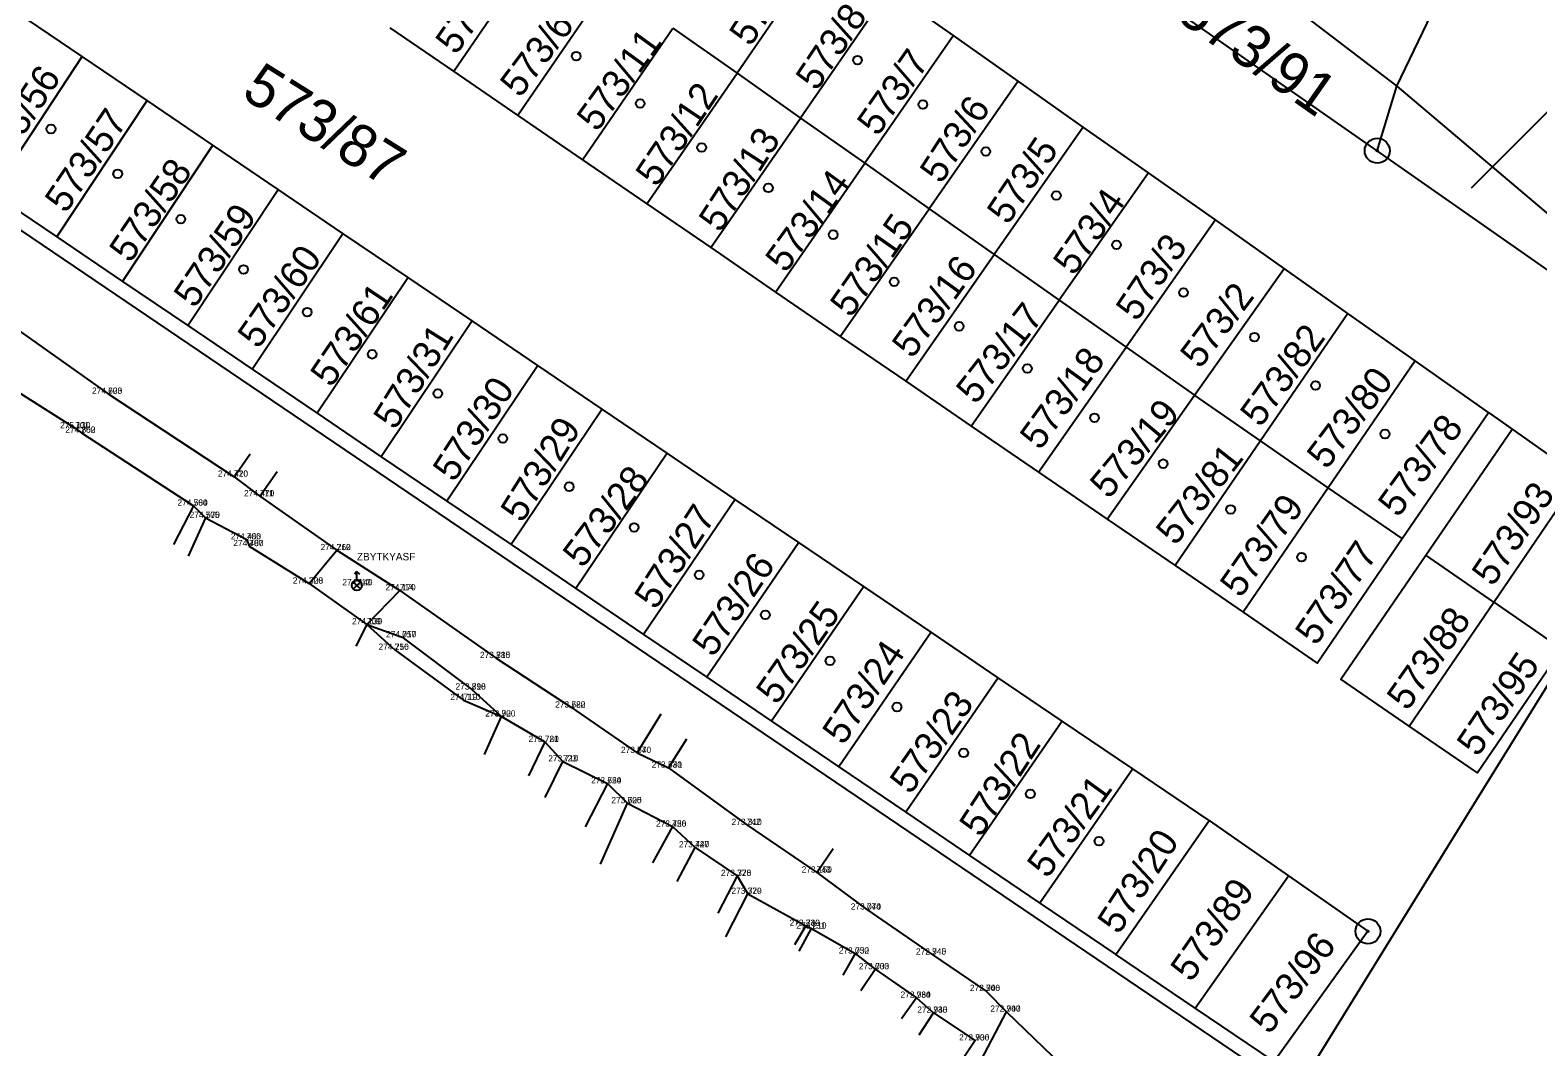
# Model space of a CAD drawing. Extents: x -776701 to -776081, y -974398 to -973771.
# Drawn here: x -776402.9 to -776342.5, y -974069 to -974028.3 of the extents above; entities that cross this region are included whole.
import ezdxf

# ---------------------------------------------------------------- set-up
doc = ezdxf.new("R2010")
doc.units = 0
for name, color, linetype in [('1 Body-bod', 7, 'Continuous'), ('10 Silnice-chodniky', 7, 'Continuous'), ('11 Rozhrani-nezpev zpev schody', 7, 'Continuous'), ('14 Hrany-paty svahu', 7, 'Continuous'), ('2 Body-cislo', 7, 'Continuous'), ('3 Body-vyska', 7, 'Continuous'), ('40 Popis-povrch', 7, 'Continuous'), ('58 Mobiliar', 7, 'Continuous'), ('7 Ploty', 7, 'Continuous'), ('Hranice parcel', 7, 'Continuous'), ('Parcelní čísla', 7, 'Continuous'), ('Pop  PČ popisy', 7, 'Continuous'), ('Značky bodu BP', 7, 'Continuous'), ('Značky budov', 7, 'Continuous')]:
    doc.layers.add(name, color=color, linetype=linetype)

msp = doc.modelspace()

# ---------------------------------------------------------------- linework, layer by layer
at = {"layer": '1 Body-bod'}
for p, q in [((-776399.75, -974042.85), (-776399.75, -974042.85)), ((-776401.07, -974044.23), (-776401.07, -974044.23)), ((-776400.82, -974044.41), (-776400.82, -974044.41)), ((-776394.71, -974046.17), (-776394.71, -974046.17)), ((-776393.68, -974046.95), (-776393.68, -974046.95)), ((-776396.33, -974047.33), (-776396.33, -974047.33)), ((-776395.85, -974047.82), (-776395.85, -974047.82)), ((-776394.2, -974048.68), (-776394.2, -974048.68)), ((-776394.1, -974048.95), (-776394.1, -974048.95)), ((-776390.6, -974049.11), (-776390.6, -974049.11)), ((-776391.7, -974050.45), (-776391.7, -974050.45)), ((-776389.79, -974050.52), (-776389.79, -974050.52)), ((-776388.07, -974050.72), (-776388.07, -974050.72)), ((-776389.39, -974052.08), (-776389.39, -974052.08)), ((-776387.98, -974052.6), (-776387.98, -974052.6)), ((-776388.27, -974053.1), (-776388.27, -974053.1)), ((-776384.21, -974053.43), (-776384.21, -974053.43)), ((-776385.52, -974055.11), (-776385.52, -974055.11)), ((-776385.19, -974054.69), (-776385.19, -974054.69)), ((-776381.2, -974055.41), (-776381.2, -974055.41)), ((-776384, -974055.77), (-776384, -974055.77)), ((-776382.27, -974056.79), (-776382.27, -974056.79)), ((-776381.54, -974057.57), (-776381.54, -974057.57)), ((-776378.57, -974057.23), (-776378.57, -974057.23)), ((-776377.32, -974057.82), (-776377.32, -974057.82)), ((-776379.76, -974058.45), (-776379.76, -974058.45)), ((-776378.95, -974059.24), (-776378.95, -974059.24)), ((-776377.16, -974060.18), (-776377.16, -974060.18)), ((-776374.18, -974060.11), (-776374.18, -974060.11)), ((-776376.25, -974061.01), (-776376.25, -974061.01)), ((-776374.56, -974062.15), (-776374.56, -974062.15)), ((-776371.38, -974062.02), (-776371.38, -974062.02)), ((-776374.14, -974062.87), (-776374.14, -974062.87)), ((-776369.37, -974063.5), (-776369.37, -974063.5)), ((-776371.81, -974064.15), (-776371.81, -974064.15)), ((-776371.59, -974064.26), (-776371.59, -974064.26)), ((-776369.84, -974065.26), (-776369.84, -974065.26)), ((-776366.76, -974065.3), (-776366.76, -974065.3)), ((-776369.04, -974065.89), (-776369.04, -974065.89)), ((-776367.38, -974067.03), (-776367.38, -974067.03)), ((-776364.6, -974066.76), (-776364.6, -974066.76)), ((-776366.71, -974067.63), (-776366.71, -974067.63)), ((-776363.78, -974067.59), (-776363.78, -974067.59)), ((-776365.03, -974068.74), (-776365.03, -974068.74))]:
    msp.add_line(p, q, dxfattribs=at)
at = {"layer": '10 Silnice-chodniky'}
for points in [[(-776391.7, -974050.45), (-776390.6, -974049.11)], [(-776389.39, -974052.08), (-776388.07, -974050.72)], [(-776364.95, -974069.84), (-776363.78, -974067.59), (-776361.2, -974070.08), (-776356.9, -974074.58)]]:
    msp.add_lwpolyline(points, dxfattribs=at)
at = {"layer": '11 Rozhrani-nezpev zpev schody'}
for points in [[(-776401.07, -974044.23), (-776400.82, -974044.41)], [(-776394.71, -974046.17), (-776393.68, -974046.95)], [(-776396.33, -974047.33), (-776395.85, -974047.82)], [(-776389.39, -974052.08), (-776387.98, -974052.6), (-776385.19, -974054.69), (-776384, -974055.77)], [(-776382.27, -974056.79), (-776381.54, -974057.57)], [(-776378.57, -974057.23), (-776377.32, -974057.82)], [(-776379.76, -974058.45), (-776378.95, -974059.24)], [(-776377.16, -974060.18), (-776376.25, -974061.01)], [(-776374.56, -974062.15), (-776374.14, -974062.87)], [(-776371.38, -974062.02), (-776369.37, -974063.5), (-776366.76, -974065.3), (-776364.6, -974066.76), (-776363.78, -974067.59)], [(-776371.81, -974064.15), (-776371.59, -974064.26)], [(-776369.84, -974065.26), (-776369.04, -974065.89)], [(-776367.38, -974067.03), (-776366.71, -974067.63)]]:
    msp.add_lwpolyline(points, dxfattribs=at)
at = {"layer": '14 Hrany-paty svahu'}
msp.add_lwpolyline([(-776389.39, -974052.08), (-776388.27, -974053.1), (-776385.52, -974055.11), (-776384, -974055.77)], dxfattribs=at)
at = {"layer": '58 Mobiliar'}
for p, q in [((-776389.79, -974049.97), (-776389.89, -974050.07)), ((-776389.79, -974050.319), (-776389.79, -974049.97)), ((-776389.79, -974049.97), (-776389.69, -974050.07)), ((-776389.79, -974050.52), (-776389.932, -974050.378)), ((-776389.79, -974050.52), (-776389.932, -974050.662)), ((-776389.79, -974050.52), (-776389.647, -974050.378)), ((-776389.79, -974050.52), (-776389.79, -974050.52)), ((-776389.79, -974050.52), (-776389.647, -974050.662))]:
    msp.add_line(p, q, dxfattribs=at)
msp.add_circle((-776389.79, -974050.52), 0.202, dxfattribs=at)
at = {"layer": '7 Ploty'}
for p, q in [((-776394.71, -974046.17), (-776394.06, -974045.258)), ((-776393.68, -974046.95), (-776392.988, -974045.967)), ((-776396.33, -974047.33), (-776397.127, -974048.88)), ((-776395.85, -974047.82), (-776396.541, -974049.349)), ((-776389.39, -974052.08), (-776389.837, -974052.95)), ((-776378.57, -974057.23), (-776377.604, -974055.667)), ((-776377.32, -974057.82), (-776376.575, -974056.665)), ((-776371.38, -974062.02), (-776370.716, -974061.054))]:
    msp.add_line(p, q, dxfattribs=at)
for points in [[(-776408.59, -974036.52), (-776407.68, -974037.33), (-776404.71, -974039.34), (-776399.75, -974042.85), (-776394.71, -974046.17)], [(-776409.79, -974038.35), (-776407.89, -974039.38), (-776407.96, -974039.52), (-776407.33, -974039.88), (-776407.37, -974039.99), (-776405.82, -974040.96), (-776405.8, -974041.24), (-776401.07, -974044.23)], [(-776400.82, -974044.41), (-776396.33, -974047.33)], [(-776393.68, -974046.95), (-776390.6, -974049.11), (-776388.07, -974050.72), (-776384.21, -974053.43), (-776381.2, -974055.41), (-776378.57, -974057.23)], [(-776395.85, -974047.82), (-776394.2, -974048.68), (-776394.1, -974048.95), (-776391.7, -974050.45), (-776389.39, -974052.08)], [(-776384.685, -974057.289), (-776384, -974055.77), (-776382.27, -974056.79), (-776382.925, -974058.148)], [(-776382.252, -974059.006), (-776381.54, -974057.57), (-776379.76, -974058.45), (-776380.648, -974060.183)], [(-776377.32, -974057.82), (-776374.18, -974060.11), (-776371.38, -974062.02)], [(-776380.031, -974061.679), (-776378.95, -974059.24), (-776377.16, -974060.18), (-776377.96, -974061.633)], [(-776376.966, -974062.382), (-776376.25, -974061.01), (-776374.56, -974062.15), (-776375.34, -974063.649)], [(-776375.019, -974064.597), (-776374.14, -974062.87), (-776371.81, -974064.15), (-776372.264, -974064.908)], [(-776372.087, -974065.158), (-776371.59, -974064.26), (-776369.84, -974065.26), (-776370.332, -974066.124)], [(-776369.616, -974066.74), (-776369.04, -974065.89), (-776367.38, -974067.03), (-776367.989, -974067.876)], [(-776367.28, -974068.515), (-776366.71, -974067.63), (-776365.03, -974068.74), (-776365.54, -974069.5)]]:
    msp.add_lwpolyline(points, dxfattribs=at)
at = {"layer": 'Hranice parcel'}
for p, q in [((-776348.16, -974030.54), (-776338.84, -974011.12)), ((-776356.65, -974024.04), (-776348.16, -974030.54)), ((-776382.26, -974024.61), (-776385.91, -974029.95)), ((-776371.04, -974024.89), (-776374.57, -974030.02)), ((-776379.71, -974026.41), (-776383.35, -974031.71)), ((-776368.49, -974026.69), (-776372.03, -974031.81)), ((-776365.9, -974028.51), (-776368.49, -974026.69)), ((-776348.94, -974033.12), (-776357.82, -974026.92)), ((-776400.79, -974029.35), (-776403.43, -974027.56)), ((-776388.47, -974028.2), (-776385.91, -974029.95)), ((-776380.76, -974033.48), (-776377.14, -974028.21)), ((-776377.14, -974028.21), (-776374.57, -974030.02)), ((-776365.9, -974028.51), (-776369.45, -974033.62)), ((-776363.32, -974030.33), (-776365.9, -974028.51)), ((-776404.39, -974034.82), (-776400.79, -974029.35)), ((-776398.19, -974031.11), (-776400.79, -974029.35)), ((-776385.91, -974029.95), (-776383.35, -974031.71)), ((-776378.18, -974035.25), (-776374.57, -974030.02)), ((-776374.57, -974030.02), (-776372.03, -974031.81)), ((-776363.32, -974030.33), (-776366.88, -974035.44)), ((-776360.71, -974032.17), (-776363.32, -974030.33)), ((-776348.94, -974033.12), (-776348.16, -974030.54)), ((-776348.16, -974030.54), (-776334.46, -974042.11)), ((-776401.8, -974036.57), (-776398.19, -974031.11)), ((-776395.56, -974032.89), (-776398.19, -974031.11)), ((-776383.35, -974031.71), (-776380.76, -974033.48)), ((-776375.62, -974037), (-776372.03, -974031.81)), ((-776372.03, -974031.81), (-776369.45, -974033.62)), ((-776360.71, -974032.17), (-776364.27, -974037.27)), ((-776358.1, -974034), (-776360.71, -974032.17)), ((-776399.18, -974038.35), (-776395.56, -974032.89)), ((-776392.94, -974034.67), (-776395.56, -974032.89)), ((-776334.96, -974042.91), (-776348.94, -974033.12)), ((-776380.76, -974033.48), (-776378.18, -974035.25)), ((-776373.03, -974038.78), (-776369.45, -974033.62)), ((-776369.45, -974033.62), (-776366.88, -974035.44)), ((-776358.1, -974034), (-776361.67, -974039.1)), ((-776355.42, -974035.89), (-776358.1, -974034)), ((-776404.39, -974034.82), (-776401.8, -974036.57)), ((-776396.56, -974040.12), (-776392.94, -974034.67)), ((-776390.35, -974036.43), (-776392.94, -974034.67)), ((-776378.18, -974035.25), (-776375.62, -974037)), ((-776370.44, -974040.55), (-776366.88, -974035.44)), ((-776366.88, -974035.44), (-776364.27, -974037.27)), ((-776393.98, -974041.87), (-776390.35, -974036.43)), ((-776387.74, -974038.19), (-776390.35, -974036.43)), ((-776355.42, -974035.89), (-776358.99, -974040.98)), ((-776352.67, -974037.83), (-776355.42, -974035.89)), ((-776401.8, -974036.57), (-776399.18, -974038.35)), ((-776375.62, -974037), (-776373.03, -974038.78)), ((-776367.81, -974042.35), (-776364.27, -974037.27)), ((-776364.27, -974037.27), (-776361.67, -974039.1)), ((-776387.74, -974038.19), (-776391.38, -974043.63)), ((-776385.18, -974039.93), (-776387.74, -974038.19)), ((-776356.25, -974042.91), (-776352.67, -974037.83)), ((-776350.12, -974039.63), (-776352.67, -974037.83)), ((-776399.18, -974038.35), (-776396.56, -974040.12)), ((-776373.03, -974038.78), (-776370.44, -974040.55)), ((-776365.2, -974044.14), (-776361.67, -974039.1)), ((-776361.67, -974039.1), (-776358.99, -974040.98)), ((-776385.18, -974039.93), (-776388.82, -974045.37)), ((-776382.54, -974041.72), (-776385.18, -974039.93)), ((-776350.12, -974039.63), (-776353.61, -974044.74)), ((-776347.42, -974041.53), (-776350.12, -974039.63)), ((-776396.56, -974040.12), (-776393.98, -974041.87)), ((-776370.44, -974040.55), (-776367.81, -974042.35)), ((-776362.5, -974045.99), (-776358.99, -974040.98)), ((-776358.99, -974040.98), (-776356.25, -974042.91)), ((-776393.98, -974041.87), (-776391.38, -974043.63)), ((-776382.54, -974041.72), (-776386.19, -974047.15)), ((-776379.97, -974043.47), (-776382.54, -974041.72)), ((-776347.42, -974041.53), (-776350.9, -974046.61)), ((-776344.48, -974043.6), (-776347.42, -974041.53)), ((-776367.81, -974042.35), (-776365.2, -974044.14)), ((-776359.75, -974047.87), (-776356.25, -974042.91)), ((-776353.61, -974044.74), (-776356.25, -974042.91)), ((-776391.38, -974043.63), (-776388.82, -974045.37)), ((-776379.97, -974043.47), (-776383.62, -974048.89)), ((-776377.37, -974045.23), (-776379.97, -974043.47)), ((-776347.94, -974048.65), (-776344.48, -974043.6)), ((-776344.48, -974043.6), (-776343.54, -974044.26)), ((-776365.2, -974044.14), (-776362.5, -974045.99)), ((-776346.99, -974049.31), (-776343.54, -974044.26)), ((-776343.54, -974044.26), (-776340.85, -974046.16)), ((-776353.61, -974044.74), (-776357.03, -974049.73)), ((-776350.9, -974046.61), (-776353.61, -974044.74)), ((-776388.82, -974045.37), (-776386.19, -974047.15)), ((-776377.37, -974045.23), (-776381.03, -974050.64)), ((-776374.64, -974047.08), (-776377.37, -974045.23)), ((-776362.5, -974045.99), (-776359.75, -974047.87)), ((-776350.9, -974046.61), (-776354.31, -974051.59)), ((-776347.94, -974048.65), (-776350.9, -974046.61)), ((-776344.27, -974051.19), (-776340.85, -974046.16)), ((-776386.19, -974047.15), (-776383.62, -974048.89)), ((-776374.64, -974047.08), (-776378.31, -974052.49)), ((-776372.1, -974048.8), (-776374.64, -974047.08)), ((-776359.75, -974047.87), (-776357.03, -974049.73)), ((-776338.11, -974048.02), (-776344.68, -974058.65)), ((-776383.62, -974048.89), (-776381.03, -974050.64)), ((-776372.1, -974048.8), (-776375.78, -974054.2)), ((-776369.5, -974050.56), (-776372.1, -974048.8)), ((-776344.27, -974051.19), (-776346.99, -974049.31)), ((-776357.03, -974049.73), (-776354.31, -974051.59)), ((-776381.03, -974050.64), (-776378.31, -974052.49)), ((-776369.5, -974050.56), (-776373.19, -974055.96)), ((-776366.8, -974052.39), (-776369.5, -974050.56)), ((-776347.66, -974056.15), (-776344.27, -974051.19)), ((-776344.27, -974051.19), (-776341.55, -974053.07)), ((-776378.31, -974052.49), (-776375.78, -974054.2)), ((-776366.8, -974052.39), (-776370.5, -974057.78)), ((-776364.11, -974054.22), (-776366.8, -974052.39)), ((-776375.78, -974054.2), (-776373.19, -974055.96)), ((-776364.11, -974054.22), (-776367.81, -974059.6)), ((-776361.55, -974055.95), (-776364.11, -974054.22)), ((-776373.19, -974055.96), (-776370.5, -974057.78)), ((-776361.55, -974055.95), (-776365.26, -974061.33)), ((-776358.73, -974057.86), (-776361.55, -974055.95)), ((-776370.5, -974057.78), (-776367.81, -974059.6)), ((-776358.73, -974057.86), (-776362.45, -974063.24)), ((-776355.67, -974059.93), (-776358.73, -974057.86)), ((-776344.68, -974058.65), (-776352.22, -974070.86)), ((-776367.81, -974059.6), (-776365.26, -974061.33)), ((-776359.4, -974065.3), (-776355.67, -974059.93)), ((-776355.67, -974059.93), (-776352.49, -974062.15)), ((-776365.26, -974061.33), (-776362.45, -974063.24)), ((-776356.23, -974067.44), (-776352.49, -974062.15)), ((-776362.45, -974063.24), (-776359.4, -974065.3)), ((-776356.23, -974067.44), (-776359.4, -974065.3))]:
    msp.add_line(p, q, dxfattribs=at)
for points in [[(-776437.4, -973999.42), (-776442.93, -974009.42), (-776352.22, -974070.86)], [(-776354.31, -974051.59), (-776351.34, -974053.63), (-776347.94, -974048.65)], [(-776347.66, -974056.15), (-776350.39, -974054.28), (-776346.99, -974049.31)], [(-776341.55, -974053.07), (-776344.92, -974058.03), (-776347.66, -974056.15)], [(-776352.49, -974062.15), (-776349.31, -974064.37), (-776353.07, -974069.58), (-776356.23, -974067.44)]]:
    msp.add_lwpolyline(points, dxfattribs=at)
at = {"layer": 'Pop  PČ popisy'}
for p, q in [((-776343.55, -974032.99), (-776341.428, -974030.868)), ((-776345.16, -974034.6), (-776343.55, -974032.99))]:
    msp.add_line(p, q, dxfattribs=at)
at = {"layer": 'Značky bodu BP'}
for centre, radius in [((-776348.94, -974033.12), 0.5), ((-776348.94, -974033.12), 0.0303), ((-776349.31, -974064.37), 0.5), ((-776349.31, -974064.37), 0.0303)]:
    msp.add_circle(centre, radius, dxfattribs=at)
at = {"layer": 'Značky budov'}
for centre in [(-776381.007, -974029.329), (-776369.747, -974029.489), (-776378.447, -974031.229), (-776367.127, -974031.269), (-776402.037, -974032.249), (-776375.987, -974032.989), (-776364.607, -974033.149), (-776399.367, -974034.039), (-776373.317, -974034.609), (-776361.787, -974034.909), (-776396.837, -974035.859), (-776370.717, -974036.479), (-776359.377, -974036.889), (-776394.327, -974037.869), (-776368.277, -974038.369), (-776356.697, -974038.799), (-776391.777, -974039.579), (-776365.677, -974040.149), (-776353.857, -974040.579), (-776389.177, -974041.269), (-776362.947, -974041.839), (-776351.407, -974042.519), (-776386.547, -974042.839), (-776360.257, -974043.809), (-776348.627, -974044.459), (-776383.947, -974044.639), (-776357.507, -974045.649), (-776381.287, -974046.569), (-776354.807, -974047.479), (-776378.687, -974048.199), (-776351.967, -974049.389), (-776376.087, -974050.099), (-776373.437, -974051.699), (-776370.847, -974053.539), (-776368.167, -974055.389), (-776365.497, -974057.229), (-776362.827, -974058.869), (-776360.077, -974060.759)]:
    msp.add_circle(centre, 0.175, dxfattribs=at)

# ---------------------------------------------------------------- texts
at = {"layer": '2 Body-cislo'}
for s, p in [('703', (-776399.75, -974042.85)), ('701', (-776401.07, -974044.23)), ('702', (-776400.82, -974044.41)), ('710', (-776394.71, -974046.17)), ('711', (-776393.68, -974046.95)), ('704', (-776396.33, -974047.33)), ('705', (-776395.85, -974047.82)), ('706', (-776394.2, -974048.68)), ('707', (-776394.1, -974048.95)), ('712', (-776390.6, -974049.11)), ('708', (-776391.7, -974050.45)), ('713', (-776389.79, -974050.52)), ('714', (-776388.07, -974050.72)), ('709', (-776389.39, -974052.08)), ('717', (-776387.98, -974052.6)), ('716', (-776388.27, -974053.1)), ('715', (-776384.21, -974053.43)), ('718', (-776385.19, -974054.69)), ('719', (-776385.52, -974055.11)), ('722', (-776381.2, -974055.41)), ('720', (-776384, -974055.77)), ('721', (-776382.27, -974056.79)), ('723', (-776381.54, -974057.57)), ('740', (-776378.57, -974057.23)), ('741', (-776377.32, -974057.82)), ('724', (-776379.76, -974058.45)), ('725', (-776378.95, -974059.24)), ('726', (-776377.16, -974060.18)), ('742', (-776374.18, -974060.11)), ('727', (-776376.25, -974061.01)), ('743', (-776371.38, -974062.02)), ('728', (-776374.56, -974062.15)), ('729', (-776374.14, -974062.87)), ('744', (-776369.37, -974063.5)), ('730', (-776371.81, -974064.15)), ('731', (-776371.59, -974064.26)), ('732', (-776369.84, -974065.26)), ('745', (-776366.76, -974065.3)), ('733', (-776369.04, -974065.89)), ('746', (-776364.6, -974066.76)), ('734', (-776367.38, -974067.03)), ('735', (-776366.71, -974067.63)), ('747', (-776363.78, -974067.59)), ('736', (-776365.03, -974068.74))]:
    msp.add_text(s, height=0.25, dxfattribs=at).set_placement(p)
at = {"layer": '3 Body-vyska'}
for s, p in [('274.620', (-776400.395, -974042.85)), ('275.130', (-776401.672, -974044.23)), ('274.850', (-776401.465, -974044.41)), ('274.420', (-776395.355, -974046.17)), ('274.470', (-776394.308, -974046.95)), ('274.580', (-776396.975, -974047.33)), ('274.570', (-776396.485, -974047.82)), ('274.480', (-776394.838, -974048.68)), ('274.480', (-776394.738, -974048.95)), ('274.260', (-776391.245, -974049.11)), ('274.320', (-776392.357, -974050.45)), ('274.140', (-776390.373, -974050.52)), ('274.170', (-776388.647, -974050.72)), ('274.130', (-776389.985, -974052.08)), ('274.050', (-776388.625, -974052.6)), ('274.250', (-776388.922, -974053.1)), ('273.880', (-776384.864, -974053.43)), ('273.890', (-776385.841, -974054.69)), ('274.110', (-776386.051, -974055.11)), ('273.680', (-776381.851, -974055.41)), ('273.900', (-776384.651, -974055.77)), ('273.780', (-776382.915, -974056.79)), ('273.710', (-776382.129, -974057.57)), ('273.570', (-776379.218, -974057.23)), ('273.530', (-776377.986, -974057.82)), ('273.650', (-776380.413, -974058.45)), ('273.600', (-776379.601, -974059.24)), ('273.450', (-776377.813, -974060.18)), ('273.310', (-776374.788, -974060.11)), ('273.440', (-776376.897, -974061.01)), ('273.150', (-776371.982, -974062.02)), ('273.370', (-776375.213, -974062.15)), ('273.370', (-776374.793, -974062.87)), ('273.070', (-776370.015, -974063.5)), ('273.240', (-776372.467, -974064.15)), ('273.210', (-776372.196, -974064.26)), ('273.050', (-776370.497, -974065.26)), ('272.940', (-776367.405, -974065.3)), ('273.000', (-776369.694, -974065.89)), ('272.900', (-776365.249, -974066.76)), ('272.960', (-776368.025, -974067.03)), ('272.940', (-776367.355, -974067.63)), ('272.900', (-776364.429, -974067.59)), ('272.900', (-776365.679, -974068.74))]:
    msp.add_text(s, height=0.25, dxfattribs=at).set_placement(p)
at = {"layer": '40 Popis-povrch'}
msp.add_text('ZBYTKYASF', height=0.3, dxfattribs=at).set_placement((-776389.79, -974049.52))
at = {"layer": 'Parcelní čísla'}
for s, height, rotation, p in [('573/68', 1.1, 55, (-776385.819, -974029.325)), ('573/9', 1.1, 57, (-776374.028, -974028.989)), ('573/91', 1.7, 325, (-776357.047, -974027.826)), ('573/67', 1.1, 53, (-776383.26, -974031.04)), ('573/8', 1.1, 56, (-776371.384, -974030.767)), ('573/11', 1.1, 54, (-776380.175, -974032.403)), ('573/7', 1.1, 55, (-776368.939, -974032.585)), ('573/56', 1.1, 57, (-776404.058, -974033.959)), ('573/87', 1.7, 328, (-776394.47, -974030.95)), ('573/12', 1.1, 56, (-776377.794, -974034.617)), ('573/6', 1.1, 57, (-776366.398, -974034.489)), ('573/57', 1.1, 56, (-776401.444, -974035.667)), ('573/13', 1.1, 57, (-776375.248, -974036.439)), ('573/5', 1.1, 56, (-776363.724, -974036.127)), ('573/58', 1.1, 56, (-776398.864, -974037.657)), ('573/14', 1.1, 54, (-776372.625, -974038.053)), ('573/4', 1.1, 55, (-776361.089, -974038.165)), ('573/59', 1.1, 56, (-776396.284, -974039.467)), ('573/15', 1.1, 55, (-776370.019, -974039.845)), ('573/60', 1.1, 55, (-776393.739, -974041.095)), ('573/3', 1.1, 56, (-776358.564, -974039.997)), ('573/16', 1.1, 54, (-776367.555, -974041.483)), ('573/61', 1.1, 56, (-776390.814, -974042.637)), ('573/2', 1.1, 53, (-776356.03, -974041.89)), ('573/17', 1.1, 52, (-776365.016, -974043.318)), ('573/31', 1.1, 58, (-776388.263, -974044.341)), ('573/82', 1.1, 54, (-776353.615, -974044.233)), ('573/18', 1.1, 54, (-776362.435, -974045.153)), ('573/80', 1.1, 53, (-776350.96, -974045.92)), ('573/30', 1.1, 57, (-776385.898, -974046.429)), ('573/19', 1.1, 50, (-776359.688, -974047.103)), ('573/29', 1.1, 58, (-776383.173, -974048.061)), ('573/78', 1.1, 54, (-776348.095, -974047.843)), ('573/81', 1.1, 52, (-776357.016, -974048.968)), ('573/28', 1.1, 53, (-776380.75, -974049.87)), ('573/93', 1.1, 56, (-776344.314, -974050.607)), ('573/27', 1.1, 57, (-776377.828, -974051.539)), ('573/79', 1.1, 55, (-776354.409, -974051.065)), ('573/77', 1.1, 56, (-776351.384, -974052.977)), ('573/26', 1.1, 56, (-776375.524, -974053.437)), ('573/25', 1.1, 55, (-776372.979, -974055.345)), ('573/88', 1.1, 55, (-776347.729, -974055.585)), ('573/24', 1.1, 56, (-776370.314, -974056.957)), ('573/95', 1.1, 56, (-776344.914, -974057.427)), ('573/23', 1.1, 55, (-776367.629, -974058.935)), ('573/22', 1.1, 57, (-776364.818, -974060.649)), ('573/21', 1.1, 54, (-776362.145, -974062.293)), ('573/20', 1.1, 57, (-776359.288, -974064.539)), ('573/89', 1.1, 55, (-776356.389, -974066.445)), ('573/96', 1.1, 53, (-776353.25, -974068.54))]:
    msp.add_text(s, height=height, rotation=rotation, dxfattribs=at).set_placement(p)

doc.saveas('drawing.dxf')
